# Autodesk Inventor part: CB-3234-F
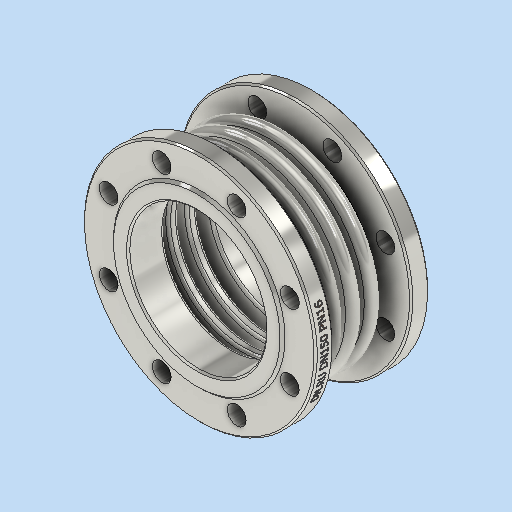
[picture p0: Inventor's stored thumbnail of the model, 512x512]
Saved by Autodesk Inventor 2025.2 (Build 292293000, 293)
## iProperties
Company: DN.RU
Created: 2026-04
Part Number: CB-3234-F
Material: Типовые
Document SubType Name: Modeling
Designer: DN.RU
Density: 5.78654 g/cm^3
Appearance: По умолчанию
Description: D140-02118
Mass: 12500 g
Surface Area: 6248.26 cm^2
Volume: 2160.19 cm^3
Author: DN.RU
Title: Компенсатор сильфонный осевой DN.ru Ду150 Ру16
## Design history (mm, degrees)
sketch "Эскиз1"
  geometry: L1 (0, 0)-(0, -72.5); L2 (92, -72.5)-(92, 0); L3 (92, 0)-(0, 0); L4 (92, 0)-(92, 0); L5 (67, 0)-(117, 0); L6 (67, -7.5)-(117, -7.5); L7 (117, 7.5)-(67, 7.5); L8 (117, -5.5)-(67, -5.5); L9 (67, 5.5)-(117, 5.5); L10 (117, -15.5)-(67, -15.5); L11 (67, -17.5)-(117, -17.5); L12 (67, -23)-(117, -23); L13 (67, -30.5)-(117, -30.5); L14 (117, -28.5)-(67, -28.5); L15 (0, -72.5)-(92, -72.5); L16 (92, -72.5)-(84, -72.5); L17 (84, -72.5)-(84, -28.5); L18 (92, -17.5)-(90, -17.5); L19 (90, -17.5)-(90, -5.5); L20 (92, 5.5)-(90, 5.5); L21 (90, 5.5)-(90, 0); L22 (0, -72.5)-(0, -47.5); L23 (0, -47.5)-(142.5, -47.5); L24 (142.5, -47.5)-(142.5, -72.5); L25 (142.5, -72.5)-(0, -72.5); L26 (92, -47.5)-(92, -62.5); L27 (92, -62.5)-(96, -62.5); L28 (96, -62.5)-(96, -47.5); L29 (96, -47.5)-(92, -47.5); L30 (92, 0)-(124.5, 0); A1 r 7.5 centre (67, 0) between (67, 7.5) and (67, -7.5); A2 r 7.5 centre (117, 0) between (117, -7.5) and (117, 7.5); A3 r 5.5 centre (67, 0) between (67, 5.5) and (67, -5.5); A4 r 5.5 centre (117, 0) between (117, -5.5) and (117, 5.5); A5 r 5.5 centre (67, -23) between (67, -17.5) and (67, -28.5); A6 r 7.5 centre (67, -23) between (67, -15.5) and (67, -30.5); A7 r 5.5 centre (117, -23) between (117, -28.5) and (117, -17.5); A8 r 7.5 centre (117, -23) between (117, -30.5) and (117, -15.5); 20 further points
  constraints: 64 end point, 17 point on circle, 14 point on line, 8 centre point, 7 parallel, 5 perpendicular, 4 tangent, 3 midpoint, 2 vertical, 1 horizontal, 25 other
  dimensions: "d0" = 72.5 distance of L1.start L1.end; "d3" = 0 distance of L2.end L4.end; "d4" = 25 distance of L4.end L5.end; "d5" = 15 diameter of A2; "d6" = 2 distance between parallel lines of L6 L8; "d9" = 23 distance of L4.end point (92, -23); "d18" = 2 distance of L18.start L18.end; "d19" = 2 distance of L20.start L20.end; "d27" = 84 distance between parallel lines of L1 L17; "d28" = 8 distance between parallel lines of L2 L17; "d29" = 25 distance of L1.end L22.end; "d30" = 142.5 distance of L22.end L23.end; "d31" = 15 distance of L26.start L26.end; "d32" = 4 distance of L27.end L26.end
revolve "Вращение1" sketch "Эскиз1" stored, may be unused: angle "d20" = 360 deg
sketch "Эскиз3" dims "d33" = 240
  geometry: L1 (0, 0)-(71.096, 29.449); L2 (0, 0)-(76.954, 0); C1 r 11.5 at (110.866, 45.922); C2 r 11.5 at (45.922, 110.866); C3 r 11.5 at (-45.922, 110.866); C4 r 11.5 at (-110.866, 45.922); C5 r 84 at (0, 0) reference; C6 r 105 at (0, 0); C7 r 142.5 at (0, 0) reference; C8 r 11.5 at (-110.866, -45.922); C9 r 11.5 at (-45.922, -110.866); C10 r 11.5 at (45.922, -110.866); C11 r 11.5 at (110.866, -45.922); 1 further point
  constraints: 9 centre point, 4 end point, 2 coincident, 1 equal length, 1 horizontal, 1 point on line, 20 other
  dimensions: "d34" = 22.5 deg angle of L2 L1; "d35" = 23 diameter of C1; "d38" = 360 deg dimension on point (0, 0) C1.centre (derived); "d40" = 210 diameter of C6
  node "Эскиз — круговой массив1" dims "d38" = 360 deg (derived)
extrude "Выдавливание1" cut sketch "Эскиз3" stored distance "d41" = 10; taper "d42" = 0 deg
extrude "Выдавливание2" cut sketch "Эскиз3" distance "d43" = 3; taper "d44" = 0 deg
chamfer "Фаска2" distance "d45" = 3; stored, may be unused: second distance "d46" = 2, angle "d47" = 45 deg
chamfer "Фаска3" distance "d48" = 2; stored, may be unused: second distance "d49" = 2, angle "d50" = 45 deg
mirror "Зеркальное отражение2"
fillet "Сопряжение2" dims "d51" = 3
node "РабПлоскость2"
sketch "Эскиз4"
  geometry: L1 (-60.476, 3.302)-(81.492, 3.302); L2 (81.492, 3.302)-(81.492, -37.818); L3 (81.492, -37.818)-(-60.476, -37.818); L4 (-60.476, -37.818)-(-60.476, 3.302); 1 further point
  constraints: 2 other
feature "Рельеф2" sketch "Эскиз4" dims "d52" = 0.1, "d53" = 0
feature "ɼ耀ɾ耀ʀ耀ʂ耀ʄ耀ʆ耀ʈ耀ʊ耀" dims "d0" = 72.5, "d3" = 0, "d4" = 25, "d5" = 15, "d6" = 2, "d7" = 20, "d9" = 23, "d10" = 10, "d12" = 10, "d18" = 2, "d19" = 2, "d20" = 360 deg, "d27" = 84, "d28" = 8, "d29" = 25, "d30" = 142.5, "d31" = 15, "d32" = 4, "d33" = 240, "d34" = 22.5 deg, "d35" = 23, "d36" = 80, "d38" = 360 deg (derived), "d40" = 210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
node "Твердое тело1"
node "Эскиз — прямоугольный массив1" dims "d9" = 23, "d12" = 10
